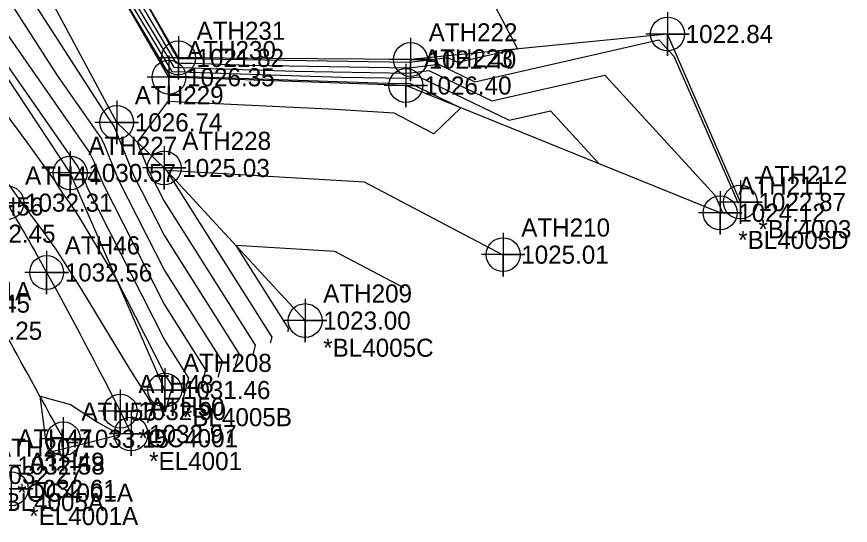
# Model space of a CAD drawing. Extents: x 1213164 to 1213550, y 766120 to 766870.
# Drawn here: x 1213428.3 to 1213543.4, y 766164.3 to 766234.6 of the extents above; entities that cross this region are included whole.
import ezdxf

# ---------------------------------------------------------------- set-up
doc = ezdxf.new("R2010")
doc.units = 0
for name, color, linetype in [('Default', 7, 'Continuous'), ('Exist DTM Breakline', 7, 'Continuous'), ('Exist DTM Breakline Cogo Comment', 7, 'Continuous'), ('Exist DTM Breakline Cogo Elevation', 7, 'Continuous'), ('Exist DTM Breakline Cogo Number', 7, 'Continuous'), ('Exist DTM Breakline Cogo Point CELL', 7, 'Continuous'), ('Exist DTM Crownline', 7, 'Continuous'), ('Exist DTM Crownline Cogo Elevation', 7, 'Continuous'), ('Exist DTM Crownline Cogo Number', 7, 'Continuous'), ('Exist DTM Crownline Cogo Point CELL', 7, 'Continuous'), ('Exist DTM Drainline Cogo Comment', 7, 'Continuous'), ('Exist DTM Drainline Cogo Elevation', 7, 'Continuous'), ('Exist DTM Drainline Cogo Number', 7, 'Continuous'), ('Exist DTM Drainline Cogo Point CELL', 7, 'Continuous'), ('Exist DTM Regular Point CELL', 7, 'Continuous'), ('Exist DTM Regular Point Cogo Comment', 7, 'Continuous'), ('Exist DTM Regular Point Cogo Elevation', 7, 'Continuous'), ('Exist DTM Regular Point Cogo Number', 7, 'Continuous'), ('Exist Hydro Stream or Body of Water', 7, 'Continuous'), ('Exist Roads EOP', 7, 'Continuous'), ('Exist Roads EOP Cogo Point CELL', 7, 'Continuous')]:
    doc.layers.add(name, color=color, linetype=linetype)

msp = doc.modelspace()

# ---------------------------------------------------------------- linework, layer by layer
at = {"layer": 'Default'}
for points in [[(1213420.06, 766304.95), (1213424.27, 766288.24), (1213424.81, 766285.7), (1213431.4, 766259.7), (1213432.04, 766256.61), (1213432.14, 766256.42), (1213434.49, 766252.57), (1213436.46, 766249.05), (1213449.69, 766226.99), (1213451.6, 766226.92), (1213452.21, 766226.91), (1213473.09, 766226.2), (1213482.19, 766226.05), (1213483.85, 766226.26), (1213496.25, 766220.26), (1213501.96, 766221.57), (1213508.68, 766214.24)], [(1213396.59, 766300.3), (1213401.19, 766291.42), (1213407.01, 766278.66), (1213411.88, 766267.99), (1213420.58, 766251.81), (1213423.73, 766246.95), (1213425.64, 766244.22), (1213440.38, 766221.3), (1213441.65, 766219.49), (1213441.73, 766219.33), (1213444.46, 766212.55), (1213448.66, 766204.27), (1213458.93, 766188.04), (1213458.45, 766186.29)], [(1213424.74, 766299.28), (1213427.56, 766285.88), (1213429.63, 766277.75), (1213434, 766256.55), (1213434.74, 766255.23), (1213435.33, 766254.27), (1213445.35, 766236.36), (1213450.26, 766228.16), (1213450.97, 766228.14), (1213452.49, 766228.12), (1213460.35, 766227.85), (1213482.44, 766227.49), (1213486.49, 766228.01), (1213491.53, 766225.56), (1213516.94, 766231.38), (1213519.02, 766229.11), (1213527.88, 766208.79)], [(1213448.81, 766180.01), (1213449.77, 766183.51), (1213448.71, 766185.18), (1213442.01, 766198.4), (1213436.88, 766206.89), (1213435.93, 766208.37), (1213435.34, 766209.2), (1213434.63, 766210.13), (1213433.49, 766211.95), (1213429.68, 766217.27), (1213417.95, 766233.12), (1213411.88, 766241.68), (1213408.5, 766246.27), (1213407.19, 766248.31), (1213403.31, 766255.2), (1213390.98, 766274.37), (1213388.98, 766277.75), (1213373.78, 766298.94)], [(1213451.22, 766181.58), (1213452.06, 766184.64), (1213448.7, 766189.95), (1213438.1, 766210.84), (1213437.62, 766212.04), (1213436.61, 766214.01), (1213420.81, 766236.7), (1213419.66, 766238.5), (1213412.69, 766248.45), (1213412.56, 766248.64), (1213412.21, 766249.3), (1213410.88, 766252.21), (1213402.59, 766266.93), (1213396.98, 766275.64), (1213390.85, 766285.97), (1213381.51, 766299)], [(1213395.96, 766296.87), (1213404.69, 766277.75), (1213411.99, 766261.76), (1213417.91, 766250.75), (1213420.05, 766247.45), (1213423.65, 766242.32), (1213433.86, 766226.44), (1213439.97, 766217.66), (1213440.36, 766216.9), (1213442.34, 766211.98), (1213448.67, 766199.5), (1213456.64, 766186.9), (1213456.04, 766184.72)], [(1213392.73, 766294.19), (1213400.2, 766281.6), (1213402.37, 766276.84), (1213412.1, 766255.53), (1213415.23, 766249.7), (1213416.37, 766247.95), (1213421.65, 766240.41), (1213427.34, 766231.57), (1213438.29, 766215.83), (1213438.99, 766214.47), (1213440.22, 766211.41), (1213448.68, 766194.73), (1213454.35, 766185.77), (1213453.63, 766183.15)], [(1213424.51, 766293.76), (1213426.19, 766285.79), (1213430.51, 766268.72), (1213433.02, 766256.58), (1213433.44, 766255.82), (1213434.91, 766253.42), (1213440.91, 766242.7), (1213449.98, 766227.57), (1213451.29, 766227.53), (1213452.35, 766227.51), (1213466.72, 766227.02), (1213482.31, 766226.77), (1213485.17, 766227.14), (1213493.89, 766222.91), (1213509.45, 766226.47), (1213524.7, 766209.84), (1213525.67, 766207.61)], [(1213427.64, 766246.13), (1213430.09, 766242.32), (1213433.84, 766240.78), (1213443.2, 766236.75), (1213449.41, 766226.4), (1213451.91, 766226.31), (1213452.07, 766226.31), (1213479.46, 766225.38), (1213482.06, 766225.33), (1213482.53, 766225.39), (1213489.61, 766221.96), (1213485.85, 766218.36), (1213480.37, 766221.23), (1213472.26, 766221.72), (1213451.12, 766222.76), (1213449.13, 766222.86), (1213444.92, 766217.23), (1213446.58, 766213.11), (1213448.64, 766209.05), (1213461.22, 766189.17), (1213460.86, 766187.86)], [(1213493.49, 766237.58), (1213497.4, 766230.1), (1213489.17, 766228.22), (1213487.81, 766228.88), (1213482.57, 766228.21), (1213453.98, 766228.67), (1213452.62, 766228.72), (1213450.66, 766228.75), (1213450.55, 766228.75), (1213449.79, 766230.01), (1213445.33, 766237.98)], [(1213446.4, 766178.44), (1213447.05, 766180.82), (1213446.42, 766181.89), (1213443.95, 766185.81), (1213437.23, 766196.93), (1213433.67, 766202.5), (1213431.43, 766205.63), (1213428.77, 766209.16), (1213428.5, 766209.6), (1213417.49, 766224.93)], [(1213495.36, 766201.65), (1213476.28, 766211.68), (1213448.95, 766213.32), (1213463.51, 766190.3), (1213463.27, 766189.43)], [(1213481.73, 766197.11), (1213472.19, 766202.12), (1213458.52, 766202.94), (1213465.8, 766191.43), (1213465.68, 766191)], [(1213432.32, 766176.08), (1213431.5, 766182.12), (1213435.69, 766180.96), (1213439.44, 766178.54), (1213442.56, 766176.8), (1213432.74, 766174.35), (1213432.44, 766175.3), (1213432.32, 766176.08)]]:
    msp.add_lwpolyline(points, dxfattribs=at)
at = {"layer": 'Exist DTM Breakline'}
for points in [[(1213525.39, 766207.47), (1213482.01, 766225.05), (1213449.3, 766226.19), (1213431.7, 766256.62), (1213419.18, 766304.88), (1213413.48, 766348.82), (1213382.31, 766373.43), (1213372.71, 766395.69), (1213369.18, 766434.58), (1213366.95, 766449.61), (1213359.43, 766466.81), (1213345.1, 766468.72)], [(1213448.72, 766182.98), (1213435.67, 766212.97), (1213412.22, 766248.51), (1213393.85, 766299.08), (1213370.87, 766342.59), (1213356.52, 766367.11), (1213355.51, 766406.8)], [(1213468.09, 766192.57), (1213448.63, 766213.66), (1213442.08, 766219.96), (1213424.22, 766253.24), (1213401.52, 766302.49), (1213377.56, 766344.05), (1213361.4, 766370.67), (1213365.74, 766393.84)]]:
    msp.add_lwpolyline(points, dxfattribs=at)
at = {"layer": 'Exist DTM Breakline Cogo Point CELL'}
for points in [[(1213449.3, 766229.19), (1213449.3, 766223.19), (1213449.3, 766226.19), (1213452.3, 766226.19), (1213446.3, 766226.19)], [(1213482.01, 766228.05), (1213482.01, 766222.05), (1213482.01, 766225.05), (1213485.01, 766225.05), (1213479.01, 766225.05)], [(1213442.08, 766222.96), (1213442.08, 766216.96), (1213442.08, 766219.96), (1213445.08, 766219.96), (1213439.08, 766219.96)], [(1213448.63, 766216.66), (1213448.63, 766210.66), (1213448.63, 766213.66), (1213451.63, 766213.66), (1213445.63, 766213.66)], [(1213435.67, 766215.97), (1213435.67, 766209.97), (1213435.67, 766212.97), (1213438.67, 766212.97), (1213432.67, 766212.97)], [(1213525.39, 766210.47), (1213525.39, 766204.47), (1213525.39, 766207.47), (1213528.39, 766207.47), (1213522.39, 766207.47)], [(1213468.09, 766195.57), (1213468.09, 766189.57), (1213468.09, 766192.57), (1213471.09, 766192.57), (1213465.09, 766192.57)], [(1213448.72, 766185.98), (1213448.72, 766179.98), (1213448.72, 766182.98), (1213451.72, 766182.98), (1213445.72, 766182.98)]]:
    msp.add_lwpolyline(points, dxfattribs=at)
for centre in [(1213449.3, 766226.19), (1213482.01, 766225.05), (1213442.08, 766219.96), (1213435.67, 766212.97), (1213448.63, 766213.66), (1213525.39, 766207.47), (1213468.09, 766192.57), (1213448.72, 766182.98)]:
    msp.add_circle(centre, 2.34, dxfattribs=at)
at = {"layer": 'Exist DTM Crownline'}
msp.add_spline([(1213434.71, 766176.25), (1213419.05, 766204.58), (1213408.83, 766222.6)], degree=3, dxfattribs=at)
at = {"layer": 'Exist DTM Crownline Cogo Point CELL'}
msp.add_lwpolyline([(1213434.71, 766179.25), (1213434.71, 766173.25), (1213434.71, 766176.25), (1213437.71, 766176.25), (1213431.71, 766176.25)], dxfattribs=at)
msp.add_circle((1213434.71, 766176.25), 2.34, dxfattribs=at)
at = {"layer": 'Exist DTM Drainline Cogo Point CELL'}
for points in [[(1213518.13, 766235.16), (1213518.13, 766229.16), (1213518.13, 766232.16), (1213521.13, 766232.16), (1213515.13, 766232.16)], [(1213450.6, 766231.86), (1213450.6, 766225.86), (1213450.6, 766228.86), (1213453.6, 766228.86), (1213447.6, 766228.86)], [(1213482.65, 766231.64), (1213482.65, 766225.64), (1213482.65, 766228.64), (1213485.65, 766228.64), (1213479.65, 766228.64)], [(1213528.18, 766211.95), (1213528.18, 766205.95), (1213528.18, 766208.95), (1213531.18, 766208.95), (1213525.18, 766208.95)]]:
    msp.add_lwpolyline(points, dxfattribs=at)
for centre in [(1213518.13, 766232.16), (1213450.6, 766228.86), (1213482.65, 766228.64), (1213528.18, 766208.95)]:
    msp.add_circle(centre, 2.34, dxfattribs=at)
at = {"layer": 'Exist DTM Regular Point CELL'}
msp.add_lwpolyline([(1213495.43, 766204.68), (1213495.43, 766198.68), (1213495.43, 766201.68), (1213498.43, 766201.68), (1213492.43, 766201.68)], dxfattribs=at)
msp.add_circle((1213495.43, 766201.68), 2.34, dxfattribs=at)
at = {"layer": 'Exist Hydro Stream or Body of Water'}
msp.add_lwpolyline([(1213528.18, 766208.95), (1213518.13, 766232.16), (1213482.65, 766228.64), (1213450.6, 766228.86), (1213434.62, 766256.54), (1213425, 766305.33), (1213420.53, 766356.32), (1213385.1, 766376.62), (1213376.32, 766397.22), (1213374.29, 766436.33), (1213371.57, 766451.85), (1213360.53, 766468.46), (1213342.81, 766469.47)], dxfattribs=at)
at = {"layer": 'Exist Roads EOP'}
msp.add_line((1213442.58, 766180.07), (1213444.06, 766176.91), dxfattribs=at)
msp.add_spline([(1213405.88, 766244.7), (1213426.93, 766208.86), (1213432.41, 766199.22), (1213442.58, 766180.07)], degree=3, dxfattribs=at)
at = {"layer": 'Exist Roads EOP Cogo Point CELL'}
for points in [[(1213426.93, 766211.86), (1213426.93, 766205.86), (1213426.93, 766208.86), (1213429.93, 766208.86), (1213423.93, 766208.86)], [(1213432.41, 766202.22), (1213432.41, 766196.22), (1213432.41, 766199.22), (1213435.41, 766199.22), (1213429.41, 766199.22)], [(1213442.58, 766183.07), (1213442.58, 766177.07), (1213442.58, 766180.07), (1213445.58, 766180.07), (1213439.58, 766180.07)], [(1213444.06, 766179.91), (1213444.06, 766173.91), (1213444.06, 766176.91), (1213447.06, 766176.91), (1213441.06, 766176.91)], [(1213425.85, 766175.55), (1213425.85, 766169.55), (1213425.85, 766172.55), (1213428.85, 766172.55), (1213422.85, 766172.55)], [(1213427.5, 766172.32), (1213427.5, 766166.32), (1213427.5, 766169.32), (1213430.5, 766169.32), (1213424.5, 766169.32)]]:
    msp.add_lwpolyline(points, dxfattribs=at)
for centre in [(1213426.93, 766208.86), (1213432.41, 766199.22), (1213442.58, 766180.07), (1213444.06, 766176.91), (1213427.5, 766169.32)]:
    msp.add_circle(centre, 2.34, dxfattribs=at)

# ---------------------------------------------------------------- texts
at = {"layer": 'Exist DTM Breakline Cogo Comment'}
for s, p in [('*BL4005D', (1213527.89, 766202.47)), ('*BL4005C', (1213470.59, 766187.57)), ('*BL4005B', (1213451.22, 766177.98)), ('*BL4005A', (1213425.28, 766166.25))]:
    msp.add_text(s, height=2.5, dxfattribs=at).set_placement(p)
at = {"layer": 'Exist DTM Breakline Cogo Elevation'}
for s, p in [('1026.35', (1213451.8, 766224.94)), ('1026.40', (1213484.51, 766223.8)), ('1026.74', (1213444.58, 766218.71)), ('1030.57', (1213438.17, 766211.72)), ('1025.03', (1213451.13, 766212.41)), ('1024.12', (1213527.89, 766206.22)), ('1023.00', (1213470.59, 766191.32)), ('1031.46', (1213451.22, 766181.73)), ('1032.27', (1213425.28, 766170))]:
    msp.add_text(s, height=2.5, dxfattribs=at).set_placement(p)
at = {"layer": 'Exist DTM Breakline Cogo Number'}
for s, p in [('ATH230', (1213451.8, 766228.69)), ('ATH223', (1213484.51, 766227.55)), ('ATH229', (1213444.58, 766222.46)), ('ATH228', (1213451.13, 766216.16)), ('ATH227', (1213438.17, 766215.47)), ('ATH211', (1213527.89, 766209.97)), ('ATH209', (1213470.59, 766195.07)), ('ATH208', (1213451.22, 766185.48)), ('ATH207', (1213425.28, 766173.75))]:
    msp.add_text(s, height=2.5, dxfattribs=at).set_placement(p)
at = {"layer": 'Exist DTM Crownline Cogo Elevation'}
for s, p in [('1032.45', (1213421.55, 766203.33)), ('1033.15', (1213437.21, 766175))]:
    msp.add_text(s, height=2.5, dxfattribs=at).set_placement(p)
at = {"layer": 'Exist DTM Crownline Cogo Number'}
for s, p in [('ATH56', (1213421.55, 766207.08)), ('ATH55', (1213437.21, 766178.75))]:
    msp.add_text(s, height=2.5, dxfattribs=at).set_placement(p)
at = {"layer": 'Exist DTM Drainline Cogo Comment'}
msp.add_text('*BL4003', height=2.5, dxfattribs=at).set_placement((1213530.68, 766203.95))
at = {"layer": 'Exist DTM Drainline Cogo Elevation'}
for s, p in [('1022.84', (1213520.63, 766230.91)), ('1021.82', (1213453.1, 766227.61)), ('1021.40', (1213485.15, 766227.39)), ('1022.87', (1213530.68, 766207.7))]:
    msp.add_text(s, height=2.5, dxfattribs=at).set_placement(p)
at = {"layer": 'Exist DTM Drainline Cogo Number'}
for s, p in [('ATH231', (1213453.1, 766231.36)), ('ATH222', (1213485.15, 766231.14)), ('ATH212', (1213530.68, 766211.45))]:
    msp.add_text(s, height=2.5, dxfattribs=at).set_placement(p)
at = {"layer": 'Exist DTM Regular Point Cogo Comment'}
for s, p in [('*OC4001A', (1213414.31, 766195.39)), ('*OC4001', (1213445.08, 766175.07)), ('*EL4001', (1213446.56, 766171.91)), ('*OC4001A', (1213428.35, 766167.55)), ('*EL4001A', (1213430, 766164.32))]:
    msp.add_text(s, height=2.5, dxfattribs=at).set_placement(p)
at = {"layer": 'Exist DTM Regular Point Cogo Elevation'}
for s, p in [('1032.31', (1213429.43, 766207.61)), ('1025.01', (1213497.93, 766200.43)), ('1032.56', (1213434.91, 766197.97)), ('1032.25', (1213419.71, 766189.92)), ('1032.90', (1213445.08, 766178.82)), ('1032.97', (1213446.56, 766175.66)), ('1032.58', (1213428.35, 766171.3)), ('1032.61', (1213430, 766168.07))]:
    msp.add_text(s, height=2.5, dxfattribs=at).set_placement(p)
at = {"layer": 'Exist DTM Regular Point Cogo Number'}
for s, p in [('ATH44', (1213429.43, 766211.36)), ('ATH210', (1213497.93, 766204.18)), ('ATH46', (1213434.91, 766201.72)), ('ATH45', (1213419.71, 766193.67)), ('ATH48', (1213445.08, 766182.57)), ('ATH50', (1213446.56, 766179.41)), ('ATH47', (1213428.35, 766175.05)), ('ATH49', (1213430, 766171.82))]:
    msp.add_text(s, height=2.5, dxfattribs=at).set_placement(p)

doc.saveas('drawing.dxf')
